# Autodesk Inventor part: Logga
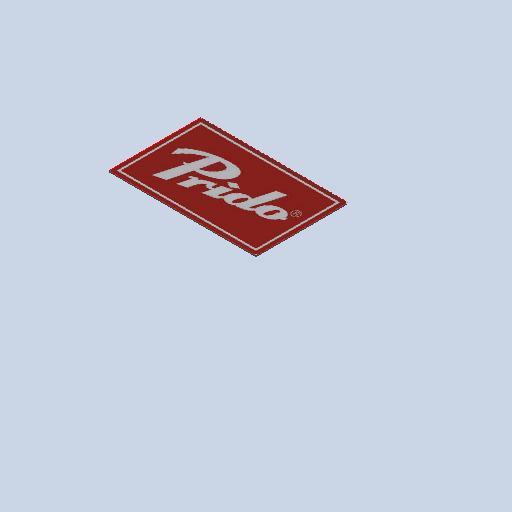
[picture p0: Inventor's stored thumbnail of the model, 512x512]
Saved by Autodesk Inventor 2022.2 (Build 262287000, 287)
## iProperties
Created: 2019-06
Part Number: Logga
Material: UHMW, Black
Document SubType Name: Modeling
Designer: cl
Density: 0.94 g/cm^3
Appearance: Smooth - Black
Author: cl
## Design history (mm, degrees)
sketch "Sketch3"
  geometry: L1 (0, 0)-(130, 0); L2 (130, 0)-(130, -80); L3 (130, -80)-(0, -80); L4 (0, -80)-(0, 0)
  constraints: 8 end point, 2 parallel, 1 horizontal, 1 perpendicular
  dimensions: "d8" = 130 distance of L2.end L3.end; "d9" = 80 distance of L1.end L2.end
extrude "Extrusion1" new body sketch "Sketch3" distance "d10" = 1; taper "d11" = 0 deg
sketch "Sketch5" dims "d8" = 130
  geometry: L1 (-130, 81.24)-(0, 81.24); L2 (0, 81.24)-(0, 0); L3 (0, 0)-(-130, 0); L4 (-130, 0)-(-130, 81.24); L5 (-130, 80)-(-130, 0) reference; 1 other entity
  constraints: 1 collinear, 2 other
  node "Image3"
body "Solid1"
